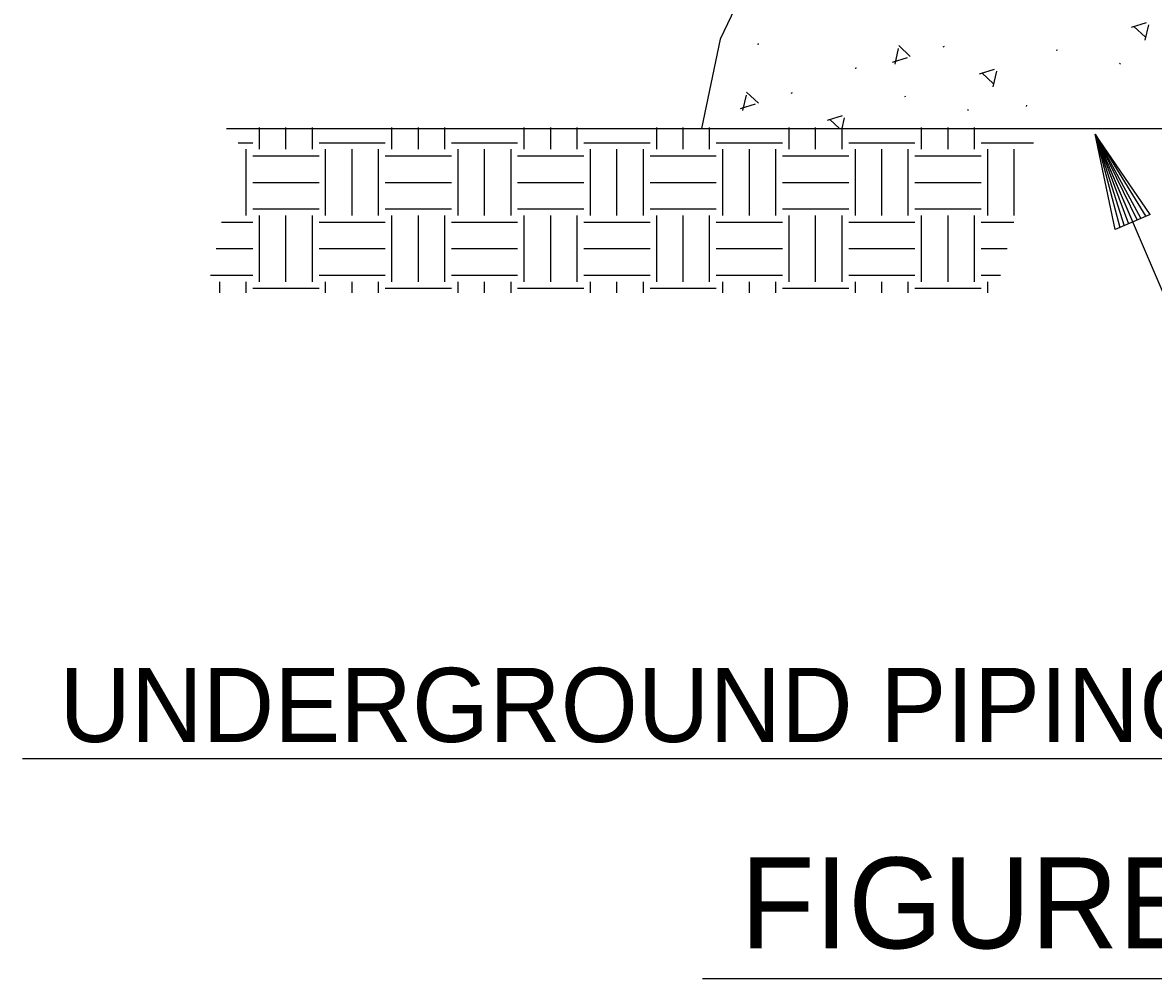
# Model space of a CAD drawing. Extents: x 10040.55 to 10045.84, y 10033.26 to 10035.76.
# Drawn here: x 10041.7874 to 10041.9653, y 10034.3241 to 10034.4745 of the extents above; entities that cross this region are included whole.
import ezdxf

# ---------------------------------------------------------------- set-up
doc = ezdxf.new("R2010")
doc.units = 0
doc.layers.add('Level 2', color=7, linetype='Continuous')

msp = doc.modelspace()

# ---------------------------------------------------------------- linework, layer by layer
at = {"layer": 'Level 2'}
for p, q in [((10041.96417, 10034.47445), (10041.96178, 10034.47372)), ((10041.96223, 10034.4739), (10041.96405, 10034.4722)), ((10041.96399, 10034.47172), (10041.96455, 10034.47416)), ((10041.9031, 10034.47124), (10041.90305, 10034.47103)), ((10041.92516, 10034.47042), (10041.92459, 10034.46799)), ((10041.92705, 10034.46918), (10041.92523, 10034.47088)), ((10041.9322, 10034.47071), (10041.93244, 10034.47078)), ((10041.95023, 10034.47018), (10041.95002, 10034.47013)), ((10041.92423, 10034.46828), (10041.92663, 10034.46901)), ((10041.96011, 10034.46797), (10041.95996, 10034.46811)), ((10041.91849, 10034.46725), (10041.91854, 10034.46746)), ((10041.94026, 10034.46714), (10041.93788, 10034.46641)), ((10041.93831, 10034.46658), (10041.94014, 10034.46488)), ((10041.94007, 10034.46441), (10041.94064, 10034.46684)), ((10041.90123, 10034.46311), (10041.90067, 10034.46068)), ((10041.90314, 10034.46185), (10041.9013, 10034.46356)), ((10041.90829, 10034.46341), (10041.90853, 10034.46348)), ((10041.92631, 10034.46288), (10041.92611, 10034.46281)), ((10041.90032, 10034.46097), (10041.90271, 10034.4617)), ((10041.9362, 10034.46065), (10041.93604, 10034.46079)), ((10041.94532, 10034.46149), (10041.94528, 10034.46128)), ((10041.91635, 10034.45982), (10041.91397, 10034.45909)), ((10041.91439, 10034.45926), (10041.9159, 10034.45785)), ((10041.91632, 10034.45785), (10041.91671, 10034.45954)), ((10041.81944, 10034.45785), (10042.07154, 10034.45785)), ((10041.82465, 10034.45456), (10041.82465, 10034.45799)), ((10041.82881, 10034.45456), (10041.82881, 10034.45799)), ((10041.83298, 10034.45456), (10041.83298, 10034.45799)), ((10041.84548, 10034.45456), (10041.84548, 10034.45799)), ((10041.84965, 10034.45456), (10041.84965, 10034.45799)), ((10041.85381, 10034.45456), (10041.85381, 10034.45799)), ((10041.86631, 10034.45456), (10041.86631, 10034.45799)), ((10041.87048, 10034.45456), (10041.87048, 10034.45799)), ((10041.87465, 10034.45456), (10041.87465, 10034.45799)), ((10041.88715, 10034.45456), (10041.88715, 10034.45799)), ((10041.89131, 10034.45456), (10041.89131, 10034.45799)), ((10041.89548, 10034.45456), (10041.89548, 10034.45799)), ((10041.90798, 10034.45456), (10041.90798, 10034.45799)), ((10041.91215, 10034.45456), (10041.91215, 10034.45799)), ((10041.91631, 10034.45456), (10041.91631, 10034.45799)), ((10041.92881, 10034.45456), (10041.92881, 10034.45799)), ((10041.93298, 10034.45456), (10041.93298, 10034.45799)), ((10041.93715, 10034.45456), (10041.93715, 10034.45799)), ((10041.96208, 10034.44313), (10041.95613, 10034.45697)), ((10041.95927, 10034.44195), (10041.95613, 10034.45697)), ((10041.96481, 10034.44431), (10041.95613, 10034.45697)), ((10041.95613, 10034.45697), (10041.9607, 10034.44254)), ((10041.95613, 10034.45697), (10041.96334, 10034.44366)), ((10041.95613, 10034.45697), (10041.96003, 10034.44226)), ((10041.95613, 10034.45697), (10041.96139, 10034.44284)), ((10041.95613, 10034.45697), (10041.96272, 10034.44342)), ((10041.95613, 10034.45697), (10041.96411, 10034.44401)), ((10041.82131, 10034.4556), (10041.8236, 10034.4556)), ((10041.83402, 10034.4556), (10041.84444, 10034.4556)), ((10041.85485, 10034.4556), (10041.86527, 10034.4556)), ((10041.87569, 10034.4556), (10041.8861, 10034.4556)), ((10041.89652, 10034.4556), (10041.90694, 10034.4556)), ((10041.91735, 10034.4556), (10041.92777, 10034.4556)), ((10041.93819, 10034.4556), (10041.94644, 10034.4556)), ((10041.82256, 10034.44415), (10041.82256, 10034.45456)), ((10041.8236, 10034.45352), (10041.83402, 10034.45352)), ((10041.83506, 10034.44415), (10041.83506, 10034.45456)), ((10041.83923, 10034.44415), (10041.83923, 10034.45456)), ((10041.8434, 10034.44415), (10041.8434, 10034.45456)), ((10041.84444, 10034.45352), (10041.85485, 10034.45352)), ((10041.8559, 10034.44415), (10041.8559, 10034.45456)), ((10041.86006, 10034.44415), (10041.86006, 10034.45456)), ((10041.86423, 10034.44415), (10041.86423, 10034.45456)), ((10041.86527, 10034.45352), (10041.87569, 10034.45352)), ((10041.87673, 10034.44415), (10041.87673, 10034.45456)), ((10041.8809, 10034.44415), (10041.8809, 10034.45456)), ((10041.88506, 10034.44415), (10041.88506, 10034.45456)), ((10041.8861, 10034.45352), (10041.89652, 10034.45352)), ((10041.89756, 10034.44415), (10041.89756, 10034.45456)), ((10041.90173, 10034.44415), (10041.90173, 10034.45456)), ((10041.9059, 10034.44415), (10041.9059, 10034.45456)), ((10041.90694, 10034.45352), (10041.91735, 10034.45352)), ((10041.9184, 10034.44415), (10041.9184, 10034.45456)), ((10041.92256, 10034.44415), (10041.92256, 10034.45456)), ((10041.92673, 10034.44415), (10041.92673, 10034.45456)), ((10041.92777, 10034.45352), (10041.93819, 10034.45352)), ((10041.93923, 10034.44415), (10041.93923, 10034.45456)), ((10041.9434, 10034.44415), (10041.9434, 10034.45456)), ((10041.8236, 10034.44935), (10041.83402, 10034.44935)), ((10041.84444, 10034.44935), (10041.85485, 10034.44935)), ((10041.86527, 10034.44935), (10041.87569, 10034.44935)), ((10041.8861, 10034.44935), (10041.89652, 10034.44935)), ((10041.90694, 10034.44935), (10041.91735, 10034.44935)), ((10041.92777, 10034.44935), (10041.93819, 10034.44935)), ((10041.8236, 10034.44519), (10041.83402, 10034.44519)), ((10041.84444, 10034.44519), (10041.85485, 10034.44519)), ((10041.86527, 10034.44519), (10041.87569, 10034.44519)), ((10041.8861, 10034.44519), (10041.89652, 10034.44519)), ((10041.90694, 10034.44519), (10041.91735, 10034.44519)), ((10041.92777, 10034.44519), (10041.93819, 10034.44519)), ((10041.8187, 10034.4431), (10041.8236, 10034.4431)), ((10041.82465, 10034.43373), (10041.82465, 10034.44415)), ((10041.82881, 10034.43373), (10041.82881, 10034.44415)), ((10041.83298, 10034.43373), (10041.83298, 10034.44415)), ((10041.83402, 10034.4431), (10041.84444, 10034.4431)), ((10041.84548, 10034.43373), (10041.84548, 10034.44415)), ((10041.84965, 10034.43373), (10041.84965, 10034.44415)), ((10041.85381, 10034.43373), (10041.85381, 10034.44415)), ((10041.85485, 10034.4431), (10041.86527, 10034.4431)), ((10041.86631, 10034.43373), (10041.86631, 10034.44415)), ((10041.87048, 10034.43373), (10041.87048, 10034.44415)), ((10041.87465, 10034.43373), (10041.87465, 10034.44415)), ((10041.87569, 10034.4431), (10041.8861, 10034.4431)), ((10041.88715, 10034.43373), (10041.88715, 10034.44415)), ((10041.89131, 10034.43373), (10041.89131, 10034.44415)), ((10041.89548, 10034.43373), (10041.89548, 10034.44415)), ((10041.89652, 10034.4431), (10041.90694, 10034.4431)), ((10041.90798, 10034.43373), (10041.90798, 10034.44415)), ((10041.91215, 10034.43373), (10041.91215, 10034.44415)), ((10041.91631, 10034.43373), (10041.91631, 10034.44415)), ((10041.91735, 10034.4431), (10041.92777, 10034.4431)), ((10041.92881, 10034.43373), (10041.92881, 10034.44415)), ((10041.93298, 10034.43373), (10041.93298, 10034.44415)), ((10041.93715, 10034.43373), (10041.93715, 10034.44415)), ((10041.93819, 10034.4431), (10041.94331, 10034.4431)), ((10041.96481, 10034.44431), (10041.95927, 10034.44195)), ((10041.81782, 10034.43894), (10041.8236, 10034.43894)), ((10041.83402, 10034.43894), (10041.84444, 10034.43894)), ((10041.85485, 10034.43894), (10041.86527, 10034.43894)), ((10041.87569, 10034.43894), (10041.8861, 10034.43894)), ((10041.89652, 10034.43894), (10041.90694, 10034.43894)), ((10041.91735, 10034.43894), (10041.92777, 10034.43894)), ((10041.93819, 10034.43894), (10041.94227, 10034.43894)), ((10041.81695, 10034.43477), (10041.8236, 10034.43477)), ((10041.83402, 10034.43477), (10041.84444, 10034.43477)), ((10041.85485, 10034.43477), (10041.86527, 10034.43477)), ((10041.87569, 10034.43477), (10041.8861, 10034.43477)), ((10041.89652, 10034.43477), (10041.90694, 10034.43477)), ((10041.91735, 10034.43477), (10041.92777, 10034.43477)), ((10041.93819, 10034.43477), (10041.94123, 10034.43477)), ((10041.8184, 10034.43198), (10041.8184, 10034.43373)), ((10041.82256, 10034.43198), (10041.82256, 10034.43373)), ((10041.8236, 10034.43269), (10041.83402, 10034.43269)), ((10041.83506, 10034.43198), (10041.83506, 10034.43373)), ((10041.83923, 10034.43198), (10041.83923, 10034.43373)), ((10041.8434, 10034.43198), (10041.8434, 10034.43373)), ((10041.84444, 10034.43269), (10041.85485, 10034.43269)), ((10041.8559, 10034.43198), (10041.8559, 10034.43373)), ((10041.86006, 10034.43198), (10041.86006, 10034.43373)), ((10041.86423, 10034.43198), (10041.86423, 10034.43373)), ((10041.86527, 10034.43269), (10041.87569, 10034.43269)), ((10041.87673, 10034.43198), (10041.87673, 10034.43373)), ((10041.8809, 10034.43198), (10041.8809, 10034.43373)), ((10041.88506, 10034.43198), (10041.88506, 10034.43373)), ((10041.8861, 10034.43269), (10041.89652, 10034.43269)), ((10041.89756, 10034.43198), (10041.89756, 10034.43373)), ((10041.90173, 10034.43198), (10041.90173, 10034.43373)), ((10041.9059, 10034.43198), (10041.9059, 10034.43373)), ((10041.90694, 10034.43269), (10041.91735, 10034.43269)), ((10041.9184, 10034.43198), (10041.9184, 10034.43373)), ((10041.92256, 10034.43198), (10041.92256, 10034.43373)), ((10041.92673, 10034.43198), (10041.92673, 10034.43373)), ((10041.92777, 10034.43269), (10041.93819, 10034.43269)), ((10041.93923, 10034.43198), (10041.93923, 10034.43373)), ((10041.78739, 10034.35869), (10042.13088, 10034.35869)), ((10041.89436, 10034.32407), (10042.03807, 10034.32407))]:
    msp.add_line(p, q, dxfattribs=at)
for points in [[(10041.98406, 10034.45819), (10041.97995, 10034.47145), (10041.97674, 10034.47923), (10041.97217, 10034.48609), (10041.96851, 10034.49388), (10041.96165, 10034.49936), (10041.94975, 10034.50577), (10041.93923, 10034.50577), (10041.93099, 10034.50622), (10041.92275, 10034.50348), (10041.91406, 10034.49936), (10041.9072, 10034.49113), (10041.90171, 10034.48152), (10041.89714, 10034.47191), (10041.89422, 10034.45785)], [(10041.98373, 10034.41927), (10041.97228, 10034.41927), (10041.95613, 10034.45697)]]:
    msp.add_lwpolyline(points, dxfattribs=at)

# ---------------------------------------------------------------- texts
for s, height, p in [('UNDERGROUND PIPING RISER-TEES', 0.0116667, (10041.79317, 10034.36128)), ('FIGURE "M"', 0.014301, (10041.90029, 10034.3288))]:
    msp.add_text(s, height=height, dxfattribs=at).set_placement(p)

doc.saveas('drawing.dxf')
